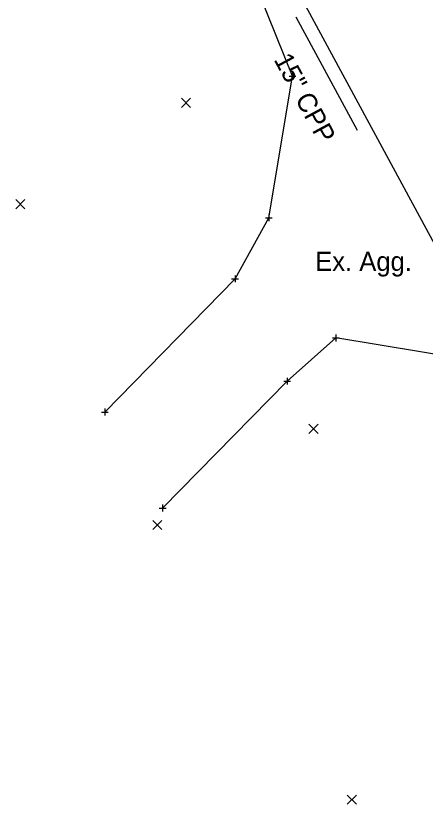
# Model space of a CAD drawing. Extents: x 2298098 to 2302860, y 557788 to 564251.
# Drawn here: x 2298368 to 2298427.9, y 563534.2 to 563649.6 of the extents above; entities that cross this region are included whole.
import ezdxf

# ---------------------------------------------------------------- set-up
doc = ezdxf.new("R2010")
doc.units = 0
for name, color, linetype in [('DR_X_Storm_Sewer', 7, 'Continuous'), ('DR_X_Text', 7, 'Continuous'), ('PV_X_Driveway', 7, 'Continuous'), ('PV_X_Text', 7, 'Continuous'), ('SV_X_Random_Point', 7, 'Continuous'), ('SV_X_Shot_Marker', 7, 'Continuous')]:
    doc.layers.add(name, color=color, linetype=linetype)

msp = doc.modelspace()

# ---------------------------------------------------------------- linework, layer by layer
at = {"layer": 'DR_X_Storm_Sewer'}
msp.add_line((2298439.7, 563596.79), (2298392.63, 563683.88), dxfattribs=at)
at = {"layer": 'DR_X_Text'}
msp.add_line((2298408.95, 563649.43), (2298417.92, 563632.83), dxfattribs=at)
at = {"layer": 'PV_X_Driveway'}
for points in [[(2298381.01, 563591.6), (2298400.05, 563611.1), (2298404.98, 563620.02), (2298408.46, 563640.74), (2298393.92, 563676.85), (2298407.82, 563686.6)], [(2298454.24, 563597.45), (2298433.96, 563599.29), (2298414.78, 563602.44), (2298407.67, 563596.12), (2298389.45, 563577.55)]]:
    msp.add_lwpolyline(points, dxfattribs=at)
at = {"layer": 'SV_X_Random_Point'}
for p, q in [((2298392.2, 563636.18), (2298393.53, 563637.51)), ((2298392.2, 563637.51), (2298393.53, 563636.18)), ((2298367.97, 563621.36), (2298369.3, 563622.69)), ((2298367.97, 563622.69), (2298369.3, 563621.36)), ((2298410.86, 563588.48), (2298412.19, 563589.81)), ((2298410.86, 563589.81), (2298412.19, 563588.48)), ((2298388, 563574.41), (2298389.33, 563575.74)), ((2298388, 563575.74), (2298389.33, 563574.41)), ((2298416.46, 563534.21), (2298417.79, 563535.54)), ((2298416.46, 563535.54), (2298417.79, 563534.21))]:
    msp.add_line(p, q, dxfattribs=at)
at = {"layer": 'SV_X_Shot_Marker'}
for p, q in [((2298407.96, 563640.74), (2298408.96, 563640.74)), ((2298408.46, 563641.24), (2298408.46, 563640.24)), ((2298408.46, 563640.74), (2298408.46, 563640.74)), ((2298404.48, 563620.02), (2298405.48, 563620.02)), ((2298404.98, 563620.52), (2298404.98, 563619.52)), ((2298404.98, 563620.02), (2298404.98, 563620.02)), ((2298400.05, 563611.6), (2298400.05, 563610.6)), ((2298399.55, 563611.1), (2298400.55, 563611.1)), ((2298400.05, 563611.1), (2298400.05, 563611.1)), ((2298414.28, 563602.44), (2298415.28, 563602.44)), ((2298414.78, 563602.94), (2298414.78, 563601.94)), ((2298414.78, 563602.44), (2298414.78, 563602.44)), ((2298407.67, 563596.62), (2298407.67, 563595.62)), ((2298407.17, 563596.12), (2298408.17, 563596.12)), ((2298407.67, 563596.12), (2298407.67, 563596.12)), ((2298381.01, 563592.1), (2298381.01, 563591.1)), ((2298380.51, 563591.6), (2298381.51, 563591.6)), ((2298381.01, 563591.6), (2298381.01, 563591.6)), ((2298389.45, 563578.05), (2298389.45, 563577.05)), ((2298388.95, 563577.55), (2298389.95, 563577.55)), ((2298389.45, 563577.55), (2298389.45, 563577.55))]:
    msp.add_line(p, q, dxfattribs=at)

# ---------------------------------------------------------------- texts
at = {"layer": 'DR_X_Text'}
msp.add_text('15" CPP', height=2.8, rotation=298.394, dxfattribs=at).set_placement((2298405.66, 563643.18))
at = {"layer": 'PV_X_Text'}
msp.add_text('Ex. Agg.', height=2.8, dxfattribs=at).set_placement((2298411.77, 563612.25))

doc.saveas('drawing.dxf')
